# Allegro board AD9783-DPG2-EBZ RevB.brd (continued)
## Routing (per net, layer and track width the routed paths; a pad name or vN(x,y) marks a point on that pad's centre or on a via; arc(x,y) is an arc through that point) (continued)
CLKN: length 12.6
  TOP w0.203: U2.4 55.02,65.25 54.61,65.66 53.89,65.66 R13.1 C21.2
CLKP: length 12.6
  TOP w0.203: C20.2 R12.2 56.6,65.66 55.88,65.66 55.52,65.3 U2.3
CSB: length 34.2
  TOP w0.203: U2.52 55.52,38.76 v1(54.48,37.72) ; XP3.5 36.96,35.56 37.47,35.05 XJP4.1
  BOTTOM w0.203: v1(54.48,37.72) 53.34,38.86 38.86,38.86 XP3.5
CVDD18: length 27.7
  TOP w0.279: U2.1 56.52,58.81 v1(57.28,59.56) 57.78,60.07 C69.1 ; 54.1,60.32 54.1,59.56 v1(54.02,59.48) U2.6
  TOP w0.508: C68.1 v1(58.8,62.36) ; TP11.1 36.7,92.33 C51.P C56.1 ; v1(37.34,84.2) C102.P
  L4PWR w0.508: 35.45,92.08 TP11.1 ; TP11.1 36.96,90.56 ; TP11.1 36.96,93.59 ; TP11.1 38.47,92.08 ; JP9.2 32.89,93.27 ; JP9.2 31.7,92.08 ; JP9.2 34.09,92.08 ; JP9.2 32.89,90.88
  BOTTOM w0.279: v1(54.02,59.48) 54.02,60.37 C105.1
  BOTTOM w0.508: v1(58.8,62.36) C68.1 ; C103.1 v1(54.1,63.25) ; R10.1 v1(59.44,68.96)
CVDD33: length 37.5
  TOP w0.279: C16.1 51.45,75.2 U1.8 ; v1(59.05,75.18) 59.04,75.2 U1.13
  TOP w0.508: C54.1 C49.P 87.5,86.11 TP7.1 ; C16.1 v1(50.67,75.18) C15.1 v1(48.89,75.18) ; C107.1 v1(59.05,75.18) C84.1 v1(60.96,75.18)
  L3PWR w0.508: JP3.2 84.89,85.85 ; JP3.2 83.69,84.66 ; JP3.2 83.69,87.05 ; JP3.2 82.5,85.85 ; 86.25,85.85 TP7.1 ; TP7.1 87.76,84.34 ; TP7.1 87.76,87.36 ; TP7.1 89.27,85.85
  L4PWR w0.508: JP3.2 83.69,87.05 ; JP3.2 84.89,85.85 ; JP3.2 83.69,84.66 ; JP3.2 82.5,85.85 ; TP7.1 87.76,87.36 ; TP7.1 89.27,85.85 ; TP7.1 86.25,85.85 ; TP7.1 87.76,84.34
D: length 2.6
  TOP w0.203: C18.2 55.49,78.64 U1.1
D0N: length 82.6
  TOP w0.127: v2(50.71,41.35) 50.71,41.37 50.98,41.64 51.53,41.64 52.45,42.57 52.45,48.31 52.52,48.39 U2.46
  BOTTOM w0.127: v2(50.71,41.35) 50.53,41.53 49.81,41.53 46.55,44.79 46.55,45.68 41.91,50.31 41.91,68.22 39.14,70.99 15.09,70.99 11.03,66.93 3.03,66.93 2.79,66.7 2.79,66.5 J18.B8
D0P: length 82.6
  TOP w0.127: U2.45 52.02,48.43 52.2,48.26 52.2,42.67 51.42,41.9 50.81,41.9 v2(50.67,42.04)
  BOTTOM w0.127: v2(50.67,42.04) 50.42,41.78 49.91,41.78 46.8,44.89 46.8,45.78 42.16,50.42 42.16,68.33 39.24,71.25 14.99,71.25 10.92,67.18 2.92,67.18 2.54,66.8 2.54,66.32 J18.A8
D1N: length 82.5
  TOP w0.127: v2(45.72,40.77) 45.97,41.02 48.64,41.02 51.44,43.81 51.44,48.01 51.52,48.09 U2.44
  BOTTOM w0.127: J18.B7 2.92,63.87 2.92,64.16 3.41,64.64 10.65,64.64 15.85,69.85 36.85,69.85 40.89,65.81 40.89,49.81 44.2,46.5 44.2,41.55 44.73,41.02 45.47,41.02 v2(45.72,40.77)
D1P: length 82.6
  TOP w0.127: U2.43 51.02,48.16 51.18,48.01 51.18,43.92 48.54,41.27 45.97,41.27 v2(45.72,41.53)
  BOTTOM w0.127: J18.A7 2.67,63.95 2.67,64.26 3.3,64.9 10.54,64.9 15.75,70.1 36.96,70.1 41.15,65.91 41.15,49.91 44.45,46.61 44.45,41.66 44.83,41.27 45.47,41.27 v2(45.72,41.53)
D2N: length 83
  TOP w0.127: U2.42 50.52,48.17 50.42,48.07 50.42,44.2 48.26,42.04 46.74,42.04 45.85,42.93 43.87,42.93 v2(43.69,42.75)
  BOTTOM w0.127: J18.B6 3.08,61.21 2.79,61.21 2.67,61.34 2.67,61.74 2.9,61.98 14.2,61.98 15.24,63.01 15.24,67.84 16.11,68.71 36.09,68.71 39.63,65.16 39.63,49.67 40.46,48.84 41.91,47.39 41.91,43.46 42.44,42.93 43.51,42.93 v2(43.69,42.75)
D2P: length 82.7
  TOP w0.127: v2(43.69,43.43) 43.94,43.18 45.95,43.18 46.84,42.29 48.15,42.29 50.16,44.3 50.16,48.13 50.02,48.27 U2.41
  BOTTOM w0.127: v2(43.69,43.43) 43.43,43.18 42.55,43.18 42.16,43.56 42.16,47.5 40.64,49.02 39.89,49.77 39.89,65.27 36.2,68.96 16,68.96 14.99,67.94 14.99,63.12 14.1,62.23 2.79,62.23 2.41,61.85 2.41,61.19 J18.A6
D3N: length 82.8
  TOP w0.127: U2.40 49.52,48.13 49.4,48.01 49.4,44.83 48.89,44.32 43.43,44.32 43.05,43.94 43.05,42.43 42.53,41.91 41.8,41.91 41.67,42.04 41.66,42.04 41.35,42.34 41.27,42.42 41.27,42.64 41.27,44.32 41.1,44.5 40.84,44.5 v2(40.77,44.58)
  BOTTOM w0.127: v2(40.77,44.58) 40.77,44.96 40,45.72 40,46.48 38.23,48.26 38.23,64.66 35.71,67.18 17,67.18 16.64,66.82 16.64,60.09 15.98,59.44 3.15,59.44 2.92,59.2 2.92,58.87 J18.B5
D3P: length 82.8
  TOP w0.127: v2(41.27,45.08) 41.27,44.68 41.53,44.43 41.53,42.54 41.53,42.52 41.76,42.29 41.77,42.29 41.9,42.16 42.43,42.16 42.8,42.54 42.8,44.05 43.33,44.58 48.79,44.58 49.15,44.94 49.15,48.01 49.02,48.13 U2.39
  BOTTOM w0.127: J18.A5 2.67,58.95 2.67,59.31 3.05,59.69 15.88,59.69 16.38,60.2 16.38,66.93 16.89,67.44 35.81,67.44 38.48,64.77 38.48,48.37 40.26,46.59 40.26,45.83 41,45.09 v2(41.27,45.09)
D4N: length 82.6
  TOP w0.127: v2(37.94,46.76) 38.33,46.76 38.61,46.48 38.61,42.16 38.99,41.78 39.75,41.78 40.13,42.16 40.13,45.47 40.51,45.85 46.48,45.85 48.39,47.75 48.39,48.13 48.52,48.27 U2.38
  BOTTOM w0.127: J18.B4 2.92,56.37 2.92,56.62 3.32,57.02 10.92,57.02 11.68,57.78 17.38,57.78 17.91,58.31 17.91,65.81 18.14,66.04 35.33,66.04 37.08,64.28 37.08,47.88 37.94,47.03 v2(37.94,46.76)
D4P: length 82.6
  TOP w0.127: v2(38.4,47.27) 38.4,47.05 38.86,46.59 38.86,42.27 39.09,42.04 39.65,42.04 39.88,42.27 39.88,45.57 40.41,46.1 46.35,46.1 48.13,47.88 48.13,48.13 48.02,48.24 U2.37
  BOTTOM w0.127: J18.A4 2.67,56.45 2.67,56.77 3.17,57.28 10.82,57.28 11.58,58.04 17.27,58.04 17.65,58.42 17.65,65.91 18.03,66.29 35.43,66.29 37.34,64.39 37.34,47.98 38.05,47.27 v2(38.4,47.27)
D5N: length 82.6
  TOP w0.127: U2.36 46.85,49.42 46.74,49.53 39.62,49.53 36.64,46.55 36.64,44.58 35.5,43.43 33.66,43.43 32.51,44.58 32.51,49.53 33.53,50.55 v2(33.53,50.93)
  BOTTOM w0.127: v2(33.53,50.93) 33.78,50.93 35.81,52.96 35.81,63.63 34.67,64.77 19.66,64.77 19.3,64.41 19.3,57.81 18.01,56.52 12.93,56.52 10.9,54.48 3.03,54.48 2.79,54.25 2.79,54 J18.B3
D5P: length 82.9
  TOP w0.127: v2(34.04,50.42) 33.76,50.42 32.77,49.42 32.77,44.68 33.76,43.69 35.39,43.69 36.39,44.68 36.39,46.65 39.52,49.78 46.74,49.78 46.87,49.92 U2.35
  BOTTOM w0.127: v2(34.04,50.42) 34.04,50.82 36.07,52.85 36.07,63.73 34.78,65.02 19.56,65.02 19.05,64.52 19.05,57.91 17.91,56.77 12.83,56.77 10.8,54.74 2.92,54.74 2.54,54.36 2.54,53.82 J18.A3
D6N: length 82.5
  TOP w0.127: v2(36.36,49.37) 36.36,49.7 36.96,50.29 45.59,50.29 45.85,50.55 46.86,50.55 46.99,50.42 U2.34
  BOTTOM w0.127: J18.B2 3.1,51.19 2.79,51.19 2.67,51.32 2.67,51.71 2.99,52.03 10.86,52.03 14.08,55.24 19.41,55.24 20.7,56.54 20.7,63.14 21.06,63.5 33.55,63.5 34.54,62.51 34.54,54.08 32,51.54 32,49.4 32.77,48.64 33.27,48.64 34.67,47.24 34.67,44.45 35.05,44.07 36.07,44.07 36.45,44.45 36.45,47.62 35.69,48.39 35.69,49.02 36.03,49.37 v2(36.36,49.37)
D6P: length 82.5
  TOP w0.127: U2.33 46.98,50.92 46.86,50.8 45.74,50.8 45.49,50.55 36.85,50.55 36.14,49.84 35.87,49.84 v2(35.86,49.84)
  BOTTOM w0.127: J18.A2 2.41,51.19 2.41,51.82 2.88,52.29 10.76,52.29 13.97,55.5 19.3,55.5 20.45,56.64 20.45,63.25 20.95,63.75 33.66,63.75 34.8,62.61 34.8,53.98 32.26,51.43 32.26,49.51 32.87,48.89 33.38,48.89 34.92,47.35 34.92,44.56 35.16,44.32 35.96,44.32 36.2,44.56 36.2,47.52 35.43,48.28 35.43,49.13 35.7,49.39 35.7,49.41 35.86,49.58 v2(35.86,49.84)
D7N: length 82.6
  TOP w0.127: v2(34.04,46.74) 34.04,47.12 34.34,47.42 34.67,47.75 34.67,49.78 36.45,51.56 41.27,51.56 41.66,51.94 45.22,51.94 45.34,52.06 45.85,52.06 45.97,51.94 45.97,51.94 46.5,51.42 U2.32
  BOTTOM w0.127: J18.B1 2.79,49 2.79,49.42 2.9,49.53 3.17,49.53 10.27,49.53 14.46,53.72 21.7,53.72 22.23,54.25 22.23,62 22.46,62.23 32.03,62.23 33.02,61.24 33.02,55.73 32.03,54.74 31.9,54.74 30.61,53.45 30.61,44.47 31.14,43.94 32.49,43.94 33.02,44.47 33.02,45.97 33.78,46.74 v2(34.04,46.74)
D7P: length 83
  TOP w0.127: U2.31 46.84,51.92 46.74,51.82 46.48,51.82 46.1,52.2 46.07,52.2 45.96,52.31 45.23,52.31 45.12,52.2 41.55,52.2 41.17,51.82 36.34,51.82 34.42,49.89 34.42,47.86 33.86,47.3 33.58,47.3 v2(33.53,47.24)
  BOTTOM w0.127: J18.A1 2.54,48.82 2.54,49.53 2.79,49.78 3.28,49.78 10.16,49.78 14.35,53.98 21.59,53.98 21.97,54.36 21.97,62.1 22.35,62.48 32.13,62.48 33.27,61.34 33.27,55.63 32.13,54.48 32,54.48 30.86,53.34 30.86,44.58 31.24,44.2 32.38,44.2 32.77,44.58 32.77,46.08 33.53,46.84 v2(33.53,47.24)
D8N: length 82.5
  TOP w0.127: U2.24 46.69,55.42 46.61,55.5 44.32,55.5 43.94,55.12 43.92,55.12 43.85,55.05 31.43,55.05 26.42,50.04 26.42,48.89 29.08,46.23 29.08,42.55 28.45,41.91 v2(28.45,41.66)
  BOTTOM w0.127: v2(28.45,41.66) 28.19,41.66 27.69,41.15 27.69,40.13 27.3,39.75 26.04,39.75 25.65,40.13 25.65,44.68 26.18,45.21 28.96,45.21 29.34,45.59 29.34,51.05 28.07,52.32 16.51,52.32 10.67,46.48 3.43,46.48 2.92,45.97 2.92,45.13 3.3,44.75 J17.B10
D8P: length 83
  TOP w0.127: v2(27.94,42.16) 28.34,42.16 28.83,42.65 28.83,46.12 26.16,48.79 26.16,50.14 31.32,55.3 43.75,55.3 44.2,55.75 46.48,55.75 46.65,55.92 U2.23
  BOTTOM w0.127: v2(27.94,42.16) 27.94,41.76 27.43,41.26 27.43,40.24 27.2,40 26.14,40 25.91,40.24 25.91,44.58 26.29,44.96 29.06,44.96 29.59,45.49 29.59,51.16 28.17,52.58 16.4,52.58 10.56,46.74 3.32,46.74 2.67,46.08 2.67,45.47 2.01,44.81 J17.A10
D9N: length 82.6
  TOP w0.127: U2.22 47.21,56.42 47.12,56.52 30.35,56.52 24,50.16 24,45.85 24.64,45.21 26.67,45.21 27.18,44.7 27.18,41.15 28.7,39.62 v2(29.08,39.62)
  BOTTOM w0.127: v2(29.08,39.62) 29.08,39.24 29.46,38.86 29.46,33.53 28.96,33.02 25.91,33.02 25.4,33.53 25.4,38.25 24.28,39.37 21.87,39.37 21.08,40.15 21.08,41.53 20.83,41.78 15.77,41.78 14.12,43.43 3.03,43.43 2.67,43.07 2.67,42.93 3.34,42.25 J17.B9
D9P: length 82.8
  TOP w0.127: U2.21 47.27,56.92 47.12,56.77 30.25,56.77 23.75,50.27 23.75,45.74 24.53,44.96 26.56,44.96 26.92,44.6 26.92,41.04 28.52,39.44 v2(28.52,39.06)
  BOTTOM w0.127: J17.A9 2.41,42.66 2.41,43.18 2.92,43.69 14.22,43.69 15.88,42.04 20.95,42.04 21.34,41.66 21.34,40.26 21.97,39.62 24.38,39.62 25.65,38.35 25.65,33.63 26.01,33.27 28.85,33.27 29.21,33.63 29.21,38.73 28.88,39.06 v2(28.52,39.06)
D10N: length 82.6
  TOP w0.127: v2(23.75,33.4) 23.9,33.4 24.53,32.77 25.91,32.77 27.56,34.42 27.56,39.24 26.42,40.39 22.48,40.39 21.34,41.53 21.34,51.05 28.19,57.91 38.73,57.91 39.12,57.53 46.63,57.53 46.74,57.42 U2.20
  BOTTOM w0.127: J17.B8 3,40.26 2.92,40.26 2.79,40.39 2.79,40.66 3.03,40.89 14.12,40.89 14.75,40.26 18.54,40.26 20.32,38.48 20.32,35.71 21.99,34.04 23.46,34.04 23.76,33.73 23.76,33.41 v2(23.75,33.4)
D10P: length 82.9
  TOP w0.127: U2.19 46.74,57.92 46.61,57.78 39.22,57.78 38.84,58.17 28.09,58.17 21.08,51.16 21.08,41.42 22.37,40.13 26.29,40.13 27.3,39.12 27.3,34.54 25.78,33.02 24.64,33.02 24.26,33.4 v2(24.26,33.91)
  BOTTOM w0.127: v2(24.26,33.91) 24,33.91 23.62,34.29 22.1,34.29 20.57,35.81 20.57,38.59 18.65,40.51 14.86,40.51 14.22,41.15 2.92,41.15 2.54,40.77 2.54,40.28 J17.A8
D11N: length 82.5
  TOP w0.127: U2.18 48.02,59.3 47.63,59.69 27.94,59.69 18.03,49.78 18.03,41.02 20.07,38.99 25.8,38.99 25.8,38.99 26.01,38.99 26.04,38.99 26.42,38.61 26.42,38.59 26.54,38.46 26.54,36.6 26.01,36.07 25.8,36.07 19.71,36.07 18.92,36.86 18.92,37.21 18.16,37.97 v2(17.78,37.97)
  BOTTOM w0.127: v2(17.78,37.97) 17.78,38.35 17.65,38.48 2.77,38.48 2.54,38.25 2.54,37.83 2.67,37.71 3.05,37.71 J17.B7
D11P: length 82.9
  TOP w0.127: v2(18.28,38.6) 18.28,38.22 19.18,37.32 19.18,36.96 19.82,36.32 25.91,36.32 26.29,36.7 26.29,38.35 25.91,38.73 19.96,38.73 17.78,40.92 17.78,49.89 27.83,59.94 47.74,59.94 48.39,59.3 48.39,59.19 48.52,59.05 U2.17
  BOTTOM w0.127: v2(18.28,38.6) 17.9,38.6 17.76,38.73 2.67,38.73 2.29,38.35 2.29,37.53 J17.A7
D12N: length 82.5
  TOP w0.127: v2(19.81,33.02) 20.32,33.02 20.83,32.51 22.33,32.51 22.86,33.04 22.86,34.16 21.97,35.05 19.56,35.05 17.02,37.59 17.02,38.01 17.02,50.82 26.65,60.45 48.01,60.45 49.15,59.31 49.15,59.18 49.02,59.06 U2.16
  BOTTOM w0.127: v2(19.81,33.02) 19.81,33.4 17.27,35.94 2.92,35.94 2.67,35.69 2.67,35.43 2.92,35.18 3.08,35.18 J17.B6
D12P: length 82.9
  TOP w0.127: v2(20.28,33.57) 20.28,33.52 20.31,33.49 20.31,33.39 20.93,32.77 22.23,32.77 22.61,33.15 22.61,34.06 21.87,34.8 19.45,34.8 19.33,34.93 16.76,37.49 16.76,38.01 16.76,38.12 16.76,38.12 16.76,50.93 26.54,60.71 48.13,60.71 49.4,59.44 49.4,59.18 49.52,59.05 U2.15
  BOTTOM w0.127: v2(20.28,33.57) 20.03,33.57 17.4,36.2 2.82,36.2 2.74,36.12 2.74,36.12 2.41,35.79 2.41,35.16 J17.A6
D13N: length 82.5
  TOP w0.127: v2(16.38,34.04) 16,34.04 14.99,35.05 14.99,50.93 25.65,61.59 47.9,61.59 48.26,61.24 48.26,61.21 50.16,59.31 50.16,59.18 50.02,59.04 U2.14
  BOTTOM w0.127: v2(16.38,34.04) 16.38,33.66 16.76,33.27 18.16,33.27 18.54,32.89 18.54,31.5 18.16,31.12 15.24,31.12 14.73,31.62 14.73,32.64 13.84,33.53 2.92,33.53 2.67,33.27 2.67,32.77 2.79,32.64 3.12,32.64 J17.B5
D13P: length 82.9
  TOP w0.127: v2(15.89,33.54) 15.89,33.79 14.73,34.95 14.73,51.03 25.55,61.85 48.01,61.85 50.42,59.44 50.42,59.18 50.52,59.08 U2.13
  BOTTOM w0.127: v2(15.89,33.54) 16.14,33.54 16.66,33.02 18.06,33.02 18.29,32.79 18.29,31.62 18.03,31.37 15.35,31.37 14.99,31.73 14.99,32.74 13.95,33.78 2.82,33.78 2.41,33.38 2.41,32.66 J17.A5
D14N: length 82.5
  TOP w0.127: U2.12 51.02,58.9 51.18,59.05 51.18,59.46 47.9,62.74 24.64,62.74 13.59,51.69 13.59,32.33 13.84,32.07 v2(13.84,32)
  BOTTOM w0.127: v2(13.84,32) 13.59,31.75 13.59,31.09 14.48,30.2 14.48,29.08 14.1,28.7 13.21,28.7 12.83,29.08 12.83,29.34 11.05,31.12 2.9,31.12 2.63,30.84 2.63,30.39 2.79,30.23 3.03,30.23 J17.B4
D14P: length 82.9
  TOP w0.127: U2.11 51.52,59.05 51.44,59.14 51.44,59.56 48.01,62.99 24.53,62.99 13.34,51.79 13.34,32.26 v2(13.08,32)
  BOTTOM w0.127: J17.A4 2.37,30.12 2.37,30.95 2.79,31.37 11.15,31.37 13.08,29.44 13.08,29.19 13.31,28.96 13.99,28.96 14.22,29.19 14.22,30.1 13.34,30.99 13.34,31.75 v2(13.08,32)
D15N: length 82.6
  TOP w0.127: v2(11.8,29.22) 11.8,29.58 12.45,30.23 12.45,52.45 24.13,64.13 47.62,64.13 52.2,59.56 52.2,59.05 52.02,58.88 U2.10
  BOTTOM w0.127: v2(11.8,29.22) 11.42,29.22 10.9,28.7 2.77,28.7 2.29,28.22 2.29,28.07 2.54,27.81 2.94,27.81 J17.B3
D15P: length 82.7
  TOP w0.127: U2.9 52.52,59.05 52.45,59.13 52.45,59.69 47.75,64.39 24.02,64.39 12.19,52.56 12.19,30.33 11.71,29.84 v2(11.3,29.84)
  BOTTOM w0.127: J17.A3 2.03,27.28 2.03,28.32 2.67,28.96 10.8,28.96 11.3,29.46 v2(11.3,29.84)
D-: length 2.6
  TOP w0.203: U1.2 54.99,78.66 C19.2
DCI_N: length 82.7
  TOP w0.127: v2(19.94,26.29) 19.94,26.56 20.04,26.67 20.83,27.45 20.83,28.7 21.97,29.84 24.64,29.84 25.78,28.7 25.78,23.62 26.92,22.48 29.46,22.48 30.61,23.62 30.61,37.65 30.61,37.65 30.61,49.02 34.16,52.58 46.71,52.58 46.86,52.42 U2.30
  BOTTOM w0.127: J17.B2 2.98,25.27 2.54,25.27 2.34,25.47 2.34,25.73 2.65,26.03 19.28,26.03 19.54,26.29 v2(19.94,26.29)
DCI_P: length 82.5
  TOP w0.127: U2.29 46.86,52.92 46.77,52.83 34.06,52.83 30.35,49.13 30.35,37.55 30.35,23.73 29.36,22.73 27.03,22.73 26.04,23.73 26.04,28.81 24.74,30.1 21.87,30.1 20.57,28.81 20.57,28.6 20.57,27.56 19.94,26.92 v2(19.43,26.92)
  BOTTOM w0.127: v2(19.43,26.92) 19.43,26.54 19.18,26.29 2.54,26.29 2.08,25.83 2.08,25.22 2.01,25.15 J17.A2
DCO_N: length 33.1
  TOP w0.127: v2(27.3,49.1) 27.5,49.29 27.51,49.29 27.62,49.4 28.17,49.4 32.49,53.72 43.94,53.72 44.76,54.54 46.68,54.54 46.81,54.42 U2.26
  BOTTOM w0.127: v2(27.3,49.1) 27.5,49.29 27.51,49.29 27.62,49.4 27.91,49.4 28.19,49.12 28.19,48.01 26.8,46.61 21.34,46.61 20.71,47.23 U3.9
DCO_P: length 33.8
  TOP w0.127: v2(27.3,49.78) 27.43,49.66 28.07,49.66 32.38,53.98 43.84,53.98 44.66,54.8 46.74,54.8 46.86,54.92 U2.25
  BOTTOM w0.127: U3.12 20.71,45.73 21.34,46.35 26.9,46.35 28.45,47.9 28.45,49.22 28.01,49.66 27.43,49.66 v2(27.3,49.78)
INTERNAL_MISO: length 30.6
  TOP w0.203: XU1.15 41.05,25.45 41.05,23.44 v1(41.4,23.09) ; XR6.2 v1(29.59,15.62) 29.59,12.83 30.43,11.99 34.06,11.99 35.49,13.42 XU2.9
  BOTTOM w0.203: v1(29.59,15.62) 29.59,17.91 34.75,23.06 41.38,23.06 v1(41.4,23.09)
INTERNAL_MOSI: length 22.2
  TOP w0.203: XU2.1 v1(34.34,18.62) 34.14,18.82 30.12,18.82 XR6.1 ; XU1.16 41.96,24.64 42.85,23.75 42.85,23.72 v1(42.98,23.6)
  BOTTOM w0.203: v1(34.34,18.62) 34.36,18.62 35.71,19.96 41.61,19.96 42.98,21.34 v1(42.98,23.6)
INTERNAL_SCK: length 34.7
  TOP w0.203: v1(29.08,11.2) 33.96,11.2 35.53,12.77 XU2.10 ; XU1.17 42.39,26.86 42.65,26.6 42.65,26.52 42.77,26.4 v1(42.77,25.1)
  BOTTOM w0.203: v1(29.08,11.2) 28.22,12.06 28.22,17.68 35.33,24.79 42.47,24.79 v1(42.77,25.1)
INTERNAL_SLAVE_SS: length 24.9
  TOP w0.203: v1(36.5,25.7) 37.15,26.36 XU1.10
  TOP w0.508: XU2.24 v1(45.63,12.77)
  BOTTOM w0.508: v1(36.5,25.7) 36.78,25.98 43.1,25.98 44.53,24.56 44.53,24.56 45,24.08 45.01,24.08 46.23,22.86 46.23,14.48 46.44,14.27 46.44,13.6 46.23,13.38 46.23,13.37 v1(45.63,12.77)
IOUT1N: length 3.5
  TOP w0.203: JP5.1 70.36,55.4 70.74,55.78 L11.1
IOUT1P: length 3.2
  TOP w0.203: JP4.1 70.36,60.25 70.74,59.87 L10.1
IOUT2N: length 3.4
  TOP w0.203: JP7.1 70.41,52.15 70.74,51.82 L9.1
IOUT2P: length 3.5
  TOP w0.203: L8.1 70.74,47.37 70.51,47.14 JP6.1
IRQ: length 7
  TOP w0.203: XU1.5 38.56,29.26 35.43,32.38 TP14.1
PGOOD18: length 7.9
  TOP w0.203: R20.2 55.37,113.28 55.37,112.78 54.23,111.63 54.23,108.71 54.86,108.08 VR1.12
PGOOD33: length 6.8
  TOP w0.203: VR1.29 54.86,99.82 54.48,99.44 54.48,96.77 55.24,96.01 55.24,95.63 R22.2
Q1_N: length 39.5
  TOP w0.127: J17.B1 2.79,21.54 2.79,21.34 3.17,20.95 9.78,20.95 17.27,28.45 17.27,34.31 15.49,36.09 15.49,37.7 15.75,37.95 15.75,43.96 15.49,44.22 15.49,45.09 15.88,45.47 v2(15.88,45.72)
  BOTTOM w0.127: U3.2 17.4,46.23 17.27,46.1 16.64,46.1 16.26,45.72 v2(15.88,45.72)
Q1_P: length 39.6
  TOP w0.127: v2(16.13,44.96) 15.75,44.58 15.75,44.32 16,44.07 16,37.85 15.75,37.59 15.75,36.2 17.53,34.42 17.53,28.34 9.88,20.7 3.07,20.7 2.54,21.23 2.54,21.59 2.01,22.12 J17.A1
  BOTTOM w0.127: v2(16.13,44.96) 16.26,45.09 16.26,45.34 16.76,45.85 17.4,45.85 17.51,45.73 U3.1
Q2_N: length 39.4
  TOP w0.127: v2(11.68,45.97) 11.43,45.97 11.05,46.35 11.05,60.45 13.34,62.74 13.34,67.69 11.68,69.34 7.34,69.34 7.11,69.57 7.11,70.1 7.24,70.23 7.45,70.23 J18.D10
  BOTTOM w0.127: U3.4 17.51,47.23 17.4,47.12 15.62,47.12 13.59,45.09 12.19,45.09 11.68,45.59 v2(11.68,45.97)
Q2_P: length 39.6
  TOP w0.127: v2(11.1,45.41) 11.1,45.94 10.8,46.25 10.8,60.56 13.08,62.84 13.08,67.59 11.58,69.09 7.24,69.09 6.86,69.47 6.86,70.43 J18.C10
  BOTTOM w0.127: U3.3 17.66,46.73 17.53,46.86 15.73,46.86 13.69,44.83 12.09,44.83 12.01,44.91 11.5,45.41 v2(11.1,45.41)
SCLK: length 24.6
  TOP w0.203: U2.51 55.02,39.78 53.72,38.48 46.1,38.48 XP3.2 44.07,36.45 XJP5.1
SDIO: length 25.9
  TOP w0.203: XJP1.1 41.91,35.56 42.04,35.69 XP3.3 44.32,39.24 52.96,39.24 54.64,40.92 54.64,48.21 54.52,48.33 U2.50
SDO: length 27.6
  TOP w0.203: XJP3.1 39.75,35.43 39.5,35.69 XP3.4 42.42,39.88 52.2,39.88 54.25,41.94 54.25,48.06 54.02,48.29 U2.49
SYNC: length 11.5
  TOP w0.203: TP2.1 57.06,104.27 VR1.5
UNNAMED_3_ICSY89833_I43_Q0: length 2.4
  BOTTOM w0.203: R1.1 18.93,43.43 18.93,43.89 18.9,43.92 18.9,44.47 18.93,44.5 U3.15
UNNAMED_3_ICSY89833_I43_Q0N: length 2.3
  BOTTOM w0.203: U3.16 18.43,43.19 R1.2
UNNAMED_3_ICSY89833_I43_Q3: length 2.5
  BOTTOM w0.203: R30.2 18.43,49.77 U3.5
UNNAMED_3_ICSY89833_I43_Q3N: length 2.5
  BOTTOM w0.203: U3.6 18.93,49.79 R30.1
UNNAMED_4_ADL5375_I114_COMM3: length 6.3
  TOP w0.203: v1(97.54,50.42) 97.02,50.94 U4.11 ; U4.8 95.52,51.07 v1(94.87,50.42)
  BOTTOM w0.203: v1(97.54,50.42) 97.18,50.42 L1.2 95.35,50.42 v1(94.87,50.42)
UNNAMED_4_ADL5375_I114_COMM10: length 5.8
  TOP w0.203: v1(95,56.77) 95.52,56.25 U4.23 ; U4.20 97.02,56.5 v1(97.28,56.77)
  BOTTOM w0.203: v1(97.28,56.77) 97.28,56.79 L2.2 95.22,56.77 v1(95,56.77)
UNNAMED_4_ADL5375_I114_IBBN: length 18.2
  TOP w0.203: U4.22 96.02,56.18 95.99,56.21 95.99,57.05 95.63,57.4 95.3,57.4 95.27,57.43 94.72,57.43 94.7,57.4 88.01,57.4 87.54,56.93 R24.1 87.22,57.09 C26.3 82.68,57.09 R3.1 81.98,57.02 L6.2
UNNAMED_4_ADL5375_I114_IBBP: length 19
  TOP w0.203: U4.21 96.52,55.6 96.52,57.15 95.88,57.78 95.45,57.78 95.43,57.81 94.56,57.81 94.54,57.78 88.27,57.78 87.41,58.64 R24.2 87.27,58.74 C26.1 82.55,58.74 R2.2 82.11,58.8 L5.2
UNNAMED_4_ADL5375_I114_LOIN: length 3.7
  TOP w0.203: U4.4 92.35,53.34 91.59,52.58 C40.2
UNNAMED_4_ADL5375_I114_LOIP: length 5
  TOP w0.203: U4.3 94.26,53.85 v1(91.69,53.85)
  BOTTOM w0.203: v1(91.69,53.85) 91.69,56.26
UNNAMED_4_ADL5375_I114_QBBN: length 18.1
  TOP w0.203: U4.9 96.01,51.59 96.01,50.16 95.61,49.76 88.29,49.76 87.54,50.51 R23.1 84.86,50.51 C27.3 82.55,50.48 R5.1 82.23,50.67 L13.2
UNNAMED_4_ADL5375_I114_QBBP: length 18.8
  TOP w0.203: L7.2 82.11,48.64 R4.2 C27.1 84.86,48.81 R23.2 87.57,48.81 88.14,49.38 95.99,49.38 96.5,49.89 96.5,50.76 96.52,50.77 U4.10
UNNAMED_4_ADL5375_I114_RFOUT: length 3.6
  TOP w0.203: C94.1 98.27,53.85 U4.16
UNNAMED_4_CAP_I61_N1: length 6.8
  TOP w0.203: L6.1 78.32,57.21 C7.3 74.07,57.21 C48.1 72.43,57.19 L11.2
UNNAMED_4_CAP_I61_N2: length 6.7
  TOP w0.203: L5.1 78.45,58.86 C7.1 74.07,58.86 C48.2 72.3,58.89 L10.2
UNNAMED_4_CAP_I81_N1: length 6.7
  TOP w0.203: L13.1 78.32,50.48 C10.3 76.3,50.51 C98.1 72.3,50.51 L9.2
UNNAMED_4_CAP_I81_N2: length 6.7
  TOP w0.203: L7.1 78.32,48.83 C10.1 76.3,48.81 C98.2 72.3,48.81 L8.2
UNNAMED_4_CAP_I109_N2: length 8.9
  TOP w0.203: C94.2 J6.1
UNNAMED_4_CAP_I111_N1: length 32.9
  BOTTOM w0.203: C22.1 91.69,65.66 102.49,76.45 J2.1
UNNAMED_6_ADG3308_I82_A1: length 5.2
  TOP w0.203: XU1.20 41.96,30.14 42.29,30.48 43.69,30.48 44.07,30.86 44.07,31.88
UNNAMED_6_ADG3308_I82_A2: length 3
  TOP w0.203: 41.91,31.88 41.06,31.02 XU1.1
UNNAMED_6_ADG3308_I82_A3: length 3
  TOP w0.203: 39.75,31.88 40.56,31.07 XU1.2
UNNAMED_6_ADG3308_I82_A4: length 4.1
  TOP w0.203: XU1.3 40.06,30.05 39.62,30.48 38.86,30.48 37.47,31.88
UNNAMED_6_ADG3308_I82_EN: length 2.4
  TOP w0.203: XU1.8 36,27.36 XR1.1
UNNAMED_6_ADG3308_I82_VCCA: length 23.5
  TOP w0.203: XU1.19 42.84,27.86 v1(43.05,28.07) ; v1(35.81,29.97) 35.81,28.92 XR1.2
  BOTTOM w0.203: v1(35.81,29.97) 36.03,29.76 XC12.1 XC11.2 v1(43.05,28.07) 45.72,28.07 46.13,28.47 XL3.2 46.03,30.32 XCR1.A 46.03,34.29 47.12,35.37 XP3.1
UNNAMED_6_ADG3308_I82_Y4: length 6.2
  TOP w0.203: XU1.14 40.56,21.72 40.93,21.34 XU2.38
UNNAMED_6_ADG3308_I82_Y6: length 6.1
  TOP w0.203: XU2.40 39.63,24.77 39.56,24.84 XU1.12
UNNAMED_6_ADG3308_I82_Y7: length 6.1
  TOP w0.203: XU2.41 38.98,24.77 39.06,24.84 XU1.11
UNNAMED_6_CAP_I4_N2: length 16.4
  TOP w0.203: XU2.32 45.25,17.97
  TOP w0.508: 45.25,17.97 46.55,19.27 XR3.1 53.64,19.27 XY1.1 55.94,14.19 XC1.2
UNNAMED_6_CAP_I5_N2: length 13.2
  TOP w0.203: XU2.33 44.52,18.62
  TOP w0.508: 44.52,18.62 46.88,20.97 XR3.2 53.53,20.97 XY1.3 53.54,23.95 XC2.2
UNNAMED_6_CAP_I11_N2: length 2.4
  TOP w0.203: XC3.2 41.58,21.05 XU2.37
UNNAMED_6_CN6P_I38_N1: length 10.3
  TOP w0.203: XP1.1 47.02,5.59 44.98,7.62 42.16,7.62 40.28,9.5 XU2.17
UNNAMED_6_CN6P_I38_N3: length 6.8
  TOP w0.203: XP1.3 41.94,7.09 39.63,9.39 XU2.16
UNNAMED_6_CN6P_I38_N4: length 6.1
  TOP w0.203: XU2.15 38.98,5.9 XP1.4
UNNAMED_6_CN6P_I38_N5: length 16.4
  TOP w0.203: v1(43.31,8.28) 43.21,8.38 42.42,8.38 40.93,9.87 XU2.18 ; XP1.5 36.87,5.47 XR2.2
  BOTTOM w0.203: XP1.5 36.86,7.14 37.97,8.25 43.28,8.25 v1(43.31,8.28)
UNNAMED_6_DIOLED_I107_P: length 3
  TOP w0.203: XD1.A 47.12,28.75 XR4.2
UNNAMED_6_ICPIC18F4550_I2_RC2CC: length 6.9
  TOP w0.203: XR4.1 44.45,20.45 42.55,20.45 42.23,20.14 XU2.36
UNNAMED_11_AD9783_I190_FSADJ: length 2.8
  TOP w0.203: v1(57.3,47.22) 57.2,47.22 56.52,47.9 U2.54
  BOTTOM w0.203: R21.2 v1(57.3,47.22)
UNNAMED_11_AD9783_I190_RESET: length 27.8
  TOP w0.203: 59.71,26.52 59.73,26.54 C17.1 R7.2 ; 59.71,26.52 R31.2 ; 59.71,26.52 59.71,38.48 56.02,42.16 U2.53
UNNAMED_11_ADCLK905_I248_PAD: length 1.7
  BOTTOM w0.508: C14.1 54.23,76.8 54.23,76.45 v2(54.74,75.95)
UNNAMED_11_ADCLK905_I248_Q: length 5.4
  TOP w0.203: U1.12 55.49,73.54 R8.1 56.93,72.1 C20.1
UNNAMED_11_ADCLK905_I248_QN: length 5.4
  TOP w0.203: U1.11 54.99,73.53 R9.2 53.56,72.1 C21.1
UNNAMED_11_ADCLK905_I248_VREF: length 4.5
  TOP w0.279: 56.9,76.83 56.76,76.7 U1.16 ; 56.9,76.83 C13.1 ; 56.9,76.83 56.9,76.33 56.76,76.2 U1.15
UNNAMED_11_CAP_I216_N2: length 9.3
  TOP w0.203: v1(58.48,47.24) 58.29,47.24 57.22,48.31 U2.55
  BOTTOM w0.203: TP16.1 63,43.18 C91.2 59.12,46.55 58.48,47.18 v1(58.48,47.24)
UNNAMED_11_CAP_I281_N1: length 9
  TOP w0.203: C18.1 56.39,82.8 R6.1 55.88,84.84 55.37,85.34 CR4.3 56.52,85.6 57.66,84.45 T2.6
UNNAMED_11_CAP_I283_N1: length 11.4
  TOP w0.203: C19.1 54.1,82.8 R6.2 54.61,87.77 CR4.2 CR4.1 58.72,87.89 T2.4
UNNAMED_11_CNBNC5P_I5_CNTR: length 12.5
  TOP w0.203: J5.1 75.02,73.74 R38.1 75.36,73.39 T7.3 75.36,67.64 JP21.2
UNNAMED_11_CNBNC5P_I6_CNTR: length 12.9
  TOP w0.203: JP22.2 80.44,67.69 T7.1 80.44,73.52 R39.2 80.61,73.69 J7.1
UNNAMED_11_CNBNC5P_I8_CNTR: length 11.5
  TOP w0.203: J8.1 80.78,34.77 R40.1 80.44,34.58 T8.3 80.44,39.4 JP23.2
UNNAMED_11_CNBNC5P_I14_CNTR: length 12.1
  TOP w0.203: J9.1 74.74,34.77 R41.2 75.36,34.61 T8.1 75.36,39.29 JP24.2
UNNAMED_11_CNBNC5P_I288_CNTR: length 13
  TOP w0.203: J1.1 71.75,87 69.22,84.45 T2.1
UNNAMED_11_NC2PJMPROPEN_I17_S1: length 18.9
  TOP w0.203: JP21.1 75.36,66.32 T7.4 v1(75.36,62.74) ; v1(69.6,58.29) 69.32,58.57 JP4.3
  BOTTOM w0.203: v1(75.36,62.74) 77.34,62.74 77.72,62.36 77.72,59.82 77.22,59.31 74.04,59.31 72.77,58.04 70.1,58.04 69.85,58.29 v1(69.6,58.29)
UNNAMED_11_NC2PJMPROPEN_I40_S1: length 19.5
  TOP w0.203: JP5.3 69.5,57.07 v1(69.6,57.17) ; v1(80.39,62.74) 80.44,62.79 T7.6 80.44,66.27 JP22.1
  BOTTOM w0.203: v1(80.39,62.74) 78.74,62.74 78.23,62.23 78.23,59.69 77.47,58.93 74.3,58.93 72.9,57.53 70.23,57.53 69.87,57.17 v1(69.6,57.17)
UNNAMED_11_NC2PJMPROPEN_I42_S1: length 19.9
  TOP w0.203: JP23.1 80.44,40.72 T8.4 v1(80.44,44.4) ; v1(69.72,50.16) 69.42,50.47 JP7.3
  BOTTOM w0.203: v1(69.72,50.16) 69.98,49.91 72.77,49.91 74.17,48.51 77.37,48.51 78.1,47.78 78.1,47.75 78.23,47.62 78.23,44.83 78.66,44.4 v1(80.44,44.4)
UNNAMED_11_NC2PJMPROPEN_I49_S1: length 19.4
  TOP w0.203: v1(75.33,44.43) 75.33,42.86 T8.6 75.36,40.72 JP24.1 ; JP6.3 69.44,48.82 v1(69.72,49.1)
  BOTTOM w0.203: v1(69.72,49.1) 70.03,49.4 72.74,49.4 74.01,48.13 77.22,48.13 77.72,47.62 77.72,44.83 77.33,44.43 v1(75.33,44.43)
UNNAMED_11_NC3PJMPR_I22_COM: length 15.9
  TOP w0.203: U2.69 58.04,56.42 58.05,56.41 59.08,56.41 59.63,56.96 C8.3 62.17,56.96 63.84,58.64 C30.1 65.96,58.64 R34.2 66.74,59.41 JP4.2 v1(69.57,59.41)
  BOTTOM w0.203: v1(69.57,59.41) 69.57,60.35 69.34,60.58 68.36,60.58 R28.2
UNNAMED_11_NC3PJMPR_I53_COM: length 15.8
  TOP w0.203: U2.68 59.14,55.92 59.75,55.31 C8.1 62.38,55.31 C30.2 65.96,56.93 R36.2 66.66,56.24 JP5.2 v1(69.57,56.24)
  BOTTOM w0.203: R26.2 69.13,55.03 69.57,55.47 v1(69.57,56.24)
UNNAMED_11_NC3PJMPR_I55_COM: length 15.9
  TOP w0.203: U2.59 58.94,51.42 59.5,50.86 C9.1 61.95,50.86 C29.1 65.96,48.81 R35.2 66.21,48.6 66.8,48.01 68.43,48.01 JP6.2 68.48,48.01 v1(69.6,48.01)
  BOTTOM w0.203: R29.2 69.25,47.03 69.6,47.37 v1(69.6,48.01)
UNNAMED_11_NC3PJMPR_I56_COM: length 16.3
  TOP w0.203: v1(69.72,51.43) 68.58,51.43 JP7.2 66.8,51.31 66.21,50.71 R37.2 65.96,50.51 C29.2 62,52.51 C9.3 59.63,52.51 59.03,51.92 U2.60
  BOTTOM w0.203: R27.2 69.51,52.54 69.72,52.32 v1(69.72,51.43)
UNNAMED_11_RES_I65_N1: length 12.9
  TOP w0.203: U2.66 58.35,54.92 v2(58.55,55.12)
  BOTTOM w0.203: v2(58.55,55.12) 58.8,54.86 61.44,54.86 64.49,57.91 64.52,57.91 65.24,57.91 R43.2 R28.1
UNNAMED_11_RES_I66_N1: length 12.8
  TOP w0.203: U2.65 58.48,54.42 v2(58.55,54.36)
  BOTTOM w0.203: R26.1 R32.2 66.08,56.73 65.28,57.53 64.64,57.53 61.59,54.48 58.67,54.48 v2(58.55,54.36)
UNNAMED_11_RES_I70_N1: length 13.4
  TOP w0.203: U2.62 58.2,52.92 v2(58.42,52.7)
  BOTTOM w0.203: v2(58.42,52.7) 58.67,52.96 61.72,52.96 64.77,49.91 65.53,49.91 66.04,49.4 66.04,48.88 R44.2 66.19,48.73 R29.1
UNNAMED_11_RES_I71_N1: length 12.8
  TOP w0.203: U2.63 58.25,53.42 v2(58.42,53.59)
  BOTTOM w0.203: v2(58.42,53.59) 58.67,53.34 61.88,53.34 64.93,50.29 65.62,50.29 R33.2 R27.1
UNNAMED_11_RES_I272_N2: length 3.2
  TOP w0.203: T7.5 77.94,64.58 R14.2
UNNAMED_11_RES_I273_N2: length 3
  TOP w0.203: R15.2 77.94,42.86 T8.5
UNNAMED_11_RES_I277_N1: length 10.5
  TOP w0.203: R7.1 S2.4 S2.3
UNNAMED_12_ADP2114PRELIM_I1_C_1: length 2.7
  TOP w0.203: VR1.7 59.58,105.26 R25.1
UNNAMED_12_ADP2114PRELIM_I1_COM: length 2.6
  TOP w0.203: VR1.2 59.67,102.76 R42.1
UNNAMED_12_ADP2114PRELIM_I1_FRE: length 10.2
  TOP w0.203: v1(58.29,103.5) 58.05,103.26 VR1.3 ; v1(59.69,100.2) R16.1 59.82,98.55 TP1.1
  BOTTOM w0.203: v1(58.29,103.5) 59.69,102.11 v1(59.69,100.2)
UNNAMED_12_ADP2114PRELIM_I1_SS1: length 2.9
  TOP w0.203: VR1.30 55.36,98.69 C32.1
UNNAMED_12_ADP2114PRELIM_I1_SS2: length 3.5
  TOP w0.203: VR1.11 55.36,109.49 C33.1
UNNAMED_12_ADP2114PRELIM_I1_SW1: length 5.6
  TOP w0.203: VR1.24 51.3,102.26 50.8,102.76 VR1.23
  TOP w0.508: 50.8,102.76 49.12,102.76 L4.1
UNNAMED_12_ADP2114PRELIM_I1_SW3: length 7
  TOP w0.203: VR1.17 50.93,105.76 51.43,105.26 VR1.18
  TOP w0.508: 50.93,105.76 48.49,105.76 48.06,106.2 L12.1
UNNAMED_12_ADP2114PRELIM_I1_V1S: length 3.4
  TOP w0.203: R18.2 55.86,99.97 VR1.31
UNNAMED_12_ADP2114PRELIM_I1_V2S: length 3.8
  TOP w0.203: R19.2 55.86,108.95 VR1.10
UNNAMED_12_ADP2114PRELIM_I1_VDD: length 4.5
  TOP w0.203: C31.1 R17.2 57.76,105.76 VR1.8
UNNAMED_12_CAP_I32_N1: length 3.7
  TOP w0.203: C41.1 C38.1 R42.2
UNNAMED_12_CAP_I46_N1: length 3.6
  TOP w0.203: R25.2 C37.1 64.39,105.16 C36.1
UNNAMED_12_CNJMPRSHRT_I19_S1: length 7.1
  TOP w0.508: JP10.2 99.69,92.71 100.33,92.08 E1.2 JP1.1
UNNAMED_12_CNJMPRSHRT_I75_S1: length 7.1
  TOP w0.508: JP2.1 E2.2 5.21,98.55 4.57,99.19 JP11.2
UNNAMED_12_CNJMPRSHRT_I84_S1: length 7.1
  TOP w0.508: JP12.2 83.06,92.84 83.69,92.2 E3.2 JP3.1
UNNAMED_12_CNJMPRSHRT_I97_S1: length 7.1
  TOP w0.508: JP13.2 18.16,99.19 18.8,98.55 E4.2 JP8.1
UNNAMED_12_CNJMPRSHRT_I99_S1: length 7.1
  TOP w0.508: JP9.1 E5.2 32.89,98.42 32.26,99.06 JP14.2
USB_D+: length 25
  TOP w0.127: XP2.3 25.4,9.91 25.15,10.16 25.15,18.41 27.56,20.83 37.36,20.83 37.93,20.26 37.93,19.9 37.68,19.65 XU2.43
USB_D-: length 25.9
  TOP w0.127: XP2.2 24.6,9.87 24.89,10.16 24.89,18.59 27.41,21.11 37.47,21.11 38.1,20.47 38.1,20.45 38.19,20.36 38.19,19.83 38.33,19.69 XU2.42
USB_VCC: length 24.1
  TOP w0.279: 43.31,26.8 42.75,27.36 XU1.18 ; XU2.28 44.83,15.37 v1(45.09,15.62) 44.69,16.02 XU2.29
  TOP w0.381: XP2.1 v1(23.8,10.29) ; XC6.2 v1(33.44,16.78) ; XC7.2 v1(33.41,14.52) ; XU2.8 35.62,14.07 v1(35.31,14.38) 35.65,14.72 XU2.7
  TOP w0.508: v1(44.4,25.96) XC8.2 43.35,26.84 43.31,26.8 ; v1(45.09,15.62) 45.1,15.63 XC5.2 ; v1(48.67,15.44) 49.17,15.95 XC4.P ; XR2.1 v1(39.75,2.16)
  L4PWR w0.508: XP1.2 45.73,5.49 ; XP1.2 44.48,4.23 ; XP1.2 44.48,6.74 ; XP1.2 43.22,5.49
  BOTTOM w0.508: XC58.2 46.01,26.33 v1(45.59,25.91) ; XCR1.C v1(49.73,32.44) ; XC57.1 v1(45.34,24.89) ; XP1.2 v1(44.48,4.04)
VCB: length 9.8
  TOP w0.508: R12.1 R13.2 v1(54.06,66.59)
  BOTTOM w0.508: R11.1 54.06,67.09 v1(54.06,66.59) ; R11.1 C23.1 ; R11.1 C24.1 R10.2

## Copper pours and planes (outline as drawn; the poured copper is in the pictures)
AVDD5 on L3PWR: 114.3,93.6 114.3,45.97 90.04,45.97 89.53,46.48 89.53,63.12 97.79,71.37 97.79,93.6
AVDD33 on L4PWR: 96.01,93.09 113.41,93.09 113.41,22.73 84.58,22.73 59.07,22.84 59.05,22.86 59.05,34.42 53.21,40.26 53.21,42.04 53.98,42.8 53.98,58.17 57.15,58.17 62.23,63.75 62.23,78.99 96.01,78.99
DVDD18 on L3PWR: 27.81,99.69 27.94,73.53 34.04,73.53 34.04,64.13 53.34,64.13 53.34,43.05 52.83,42.55 49.02,42.55 49.02,59.82 47.62,61.21 19.68,61.21 19.68,82.17 14.22,82.17 14.22,99.69
DVDD33 on L3PWR: 0.63,99.69 11.3,99.69 11.3,80.52 18.41,80.52 18.41,60.71 46.99,60.71 48.39,59.31 48.51,41.27 52.07,41.4 51.94,21.97 76.2,21.97 76.2,1.14 0.63,1.14
V5 on TOP: 54.48,100.84 54.61,100.71 54.61,100.2 53.59,99.19 53.59,96.65 50.55,96.65 50.55,100.97 50.8,101.22 51.94,101.22 52.32,100.84
V5 on TOP: 50.55,112.27 53.34,112.27 53.85,111.76 53.85,107.82 54.36,107.31 54.48,107.31 54.48,106.05 52.58,106.05 51.82,106.81 51.82,108.2 50.55,109.47
V5 on L3PWR: 48.26,111.38 61.72,111.51 61.72,117.98 114.17,117.98 114.3,94.23 105.79,94.23 105.79,95.5 78.1,95.5 78.1,94.23 48.26,94.23
V18 on L3PWR: 12.06,118.36 12.06,100.33 45.85,100.33 45.85,116.2 45.97,116.08 54.61,116.08 54.74,115.95 54.74,113.79 60.83,113.79 60.96,113.92 60.96,118.36
V33 on L4PWR: 0.63,99.95 45.72,99.95 45.72,98.04 79.38,98.04 79.38,93.98 105.41,93.98 105.41,103.76 81.91,103.76 81.91,119.89 0.63,119.89
APLANE on TOP: 45.09,105.41 47.88,105.41 48.26,105.03 51.05,105.03 51.05,103.25 45.47,103.25 45.09,103.63
APLANE on L2GND, L5GND: 0.63,0.64 0.63,120.27 114.3,120.27 114.3,0.51
CVDD18 on L4PWR: 47.12,95.38 47.12,72.64 60.32,72.64 60.32,63.75 56.9,58.55 54.61,58.55 53.47,59.18 53.47,60.07 28.32,60.07 28.32,95.38
CVDD33 on L3PWR: 46.35,66.29 64.01,66.29 64.9,67.18 64.9,78.36 65.79,79.25 94.11,79.25 94.11,93.6 78.61,93.6 78.61,93.22 78.36,92.96 46.35,92.96
CVDD33 on L4PWR: 78.74,93.34 95.25,93.34 95.25,79.5 61.34,79.5 61.34,73.66 61.21,73.53 49.02,73.53 48.64,73.91 48.64,80.14 57.53,80.14 57.66,80.26 57.66,97.54 57.78,97.41 78.74,97.41
USB_VCC on L4PWR: 51.05,33.91 51.05,29.59 57.78,29.59 57.78,1.02 15.24,1.02 15.24,21.97 27.18,33.91

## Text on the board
BOTTOM: 10004 REV B
Ref Des/Silkscreen Top: DVDD33 | USB | DVDD18 | CVDD18 | IOUT1P | IOUT2P | RESET | IN | CLOCK | IOUT2N | IOUT1N | GND | +5V | CVDD33 | AD9783-DPG2-EBZ | AD9781-DPG2-EBZ | AD9780-DPG2-EBZ | LOCAL OSC INPUT | OUTPUT | AVDD33 | MODULATED
DIMENSION: DIFFERENTIAL IMPEDANCE = 100 OHMS +/- 10% | ARTWORK LINE WIDTH FOR | IMPEDANCE CONTROLLED LINES = 0.005" | GROUND PLANE    (LAYER 2) | POWER PLANE     (LAYER 4) | FOR LAYER 1 AND 6. | FOR LAYER 1 AND 6
PAGE_OUTLINE: REVISED J17 J18 PLACEMENT | 08NOV10 | J.C. | BOARD | HSC 10004
User.8: L2 GND
User.9: L3 PWR
User.10: IMMERSION GOLD OVER 100-200 MICROINCHES OF ELECTROLESS NICKEL. | 14.    FINISH: SURFACES SHALL HAVE ENIG FINISH PLATED WITH 2-6 MICROINCHES OF
User.11: L4 PWR
User.12: L5 GND
User.13: SECONDARY SIDE
User.17: FIGURE | SIZE | 10.0 | 16.0 | 25.0 | 40.0 | 45.0 | 60.0 | 63.0 | 75.0 | 155.0 | PLATED | NON-PLATED | FINISHED HOLES IN MILS | ALL UNITS ARE IN MILS | QTY | 100 | 449 | 120 | 16 | 6 | 25 | 15 | 4 | 2 | TOLERANCE/NOTES
